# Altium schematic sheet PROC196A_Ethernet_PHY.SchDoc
size 431 x 279 mm; Date: Not shown in title block; ApprovedBy: Not shown in title block; CheckedBy: Not shown in title block; Author: Not shown in title block; CompanyName: Not shown in title block; Engineer: Not shown in title block; Organization: Not shown in title block; Address1: Not shown in title block; Address2: Not shown in title block; Address3: Not shown in title block; Address4: Not shown in title block; DocumentNumber: 12; Revision: Use project parameter SCH_Rev; SheetNumber: 12; SheetTotal: 25; PageSetup: Record=PageOptions¦CenterHorizontal=True¦CenterVertical=True¦PrintScale=1.00¦XCorrection=1.00¦YCorrection=1.00¦PrintKind=0¦BorderSize=5000000¦LeftOffset=0¦BottomOffset=0¦Orientation=2¦PaperLength=1000¦PaperWidth=1000¦Scale=100¦PaperSource=15¦PrintQuality=600¦MediaType=1¦DitherType=10¦PaperKind=Letter¦PrintScaleMode=1
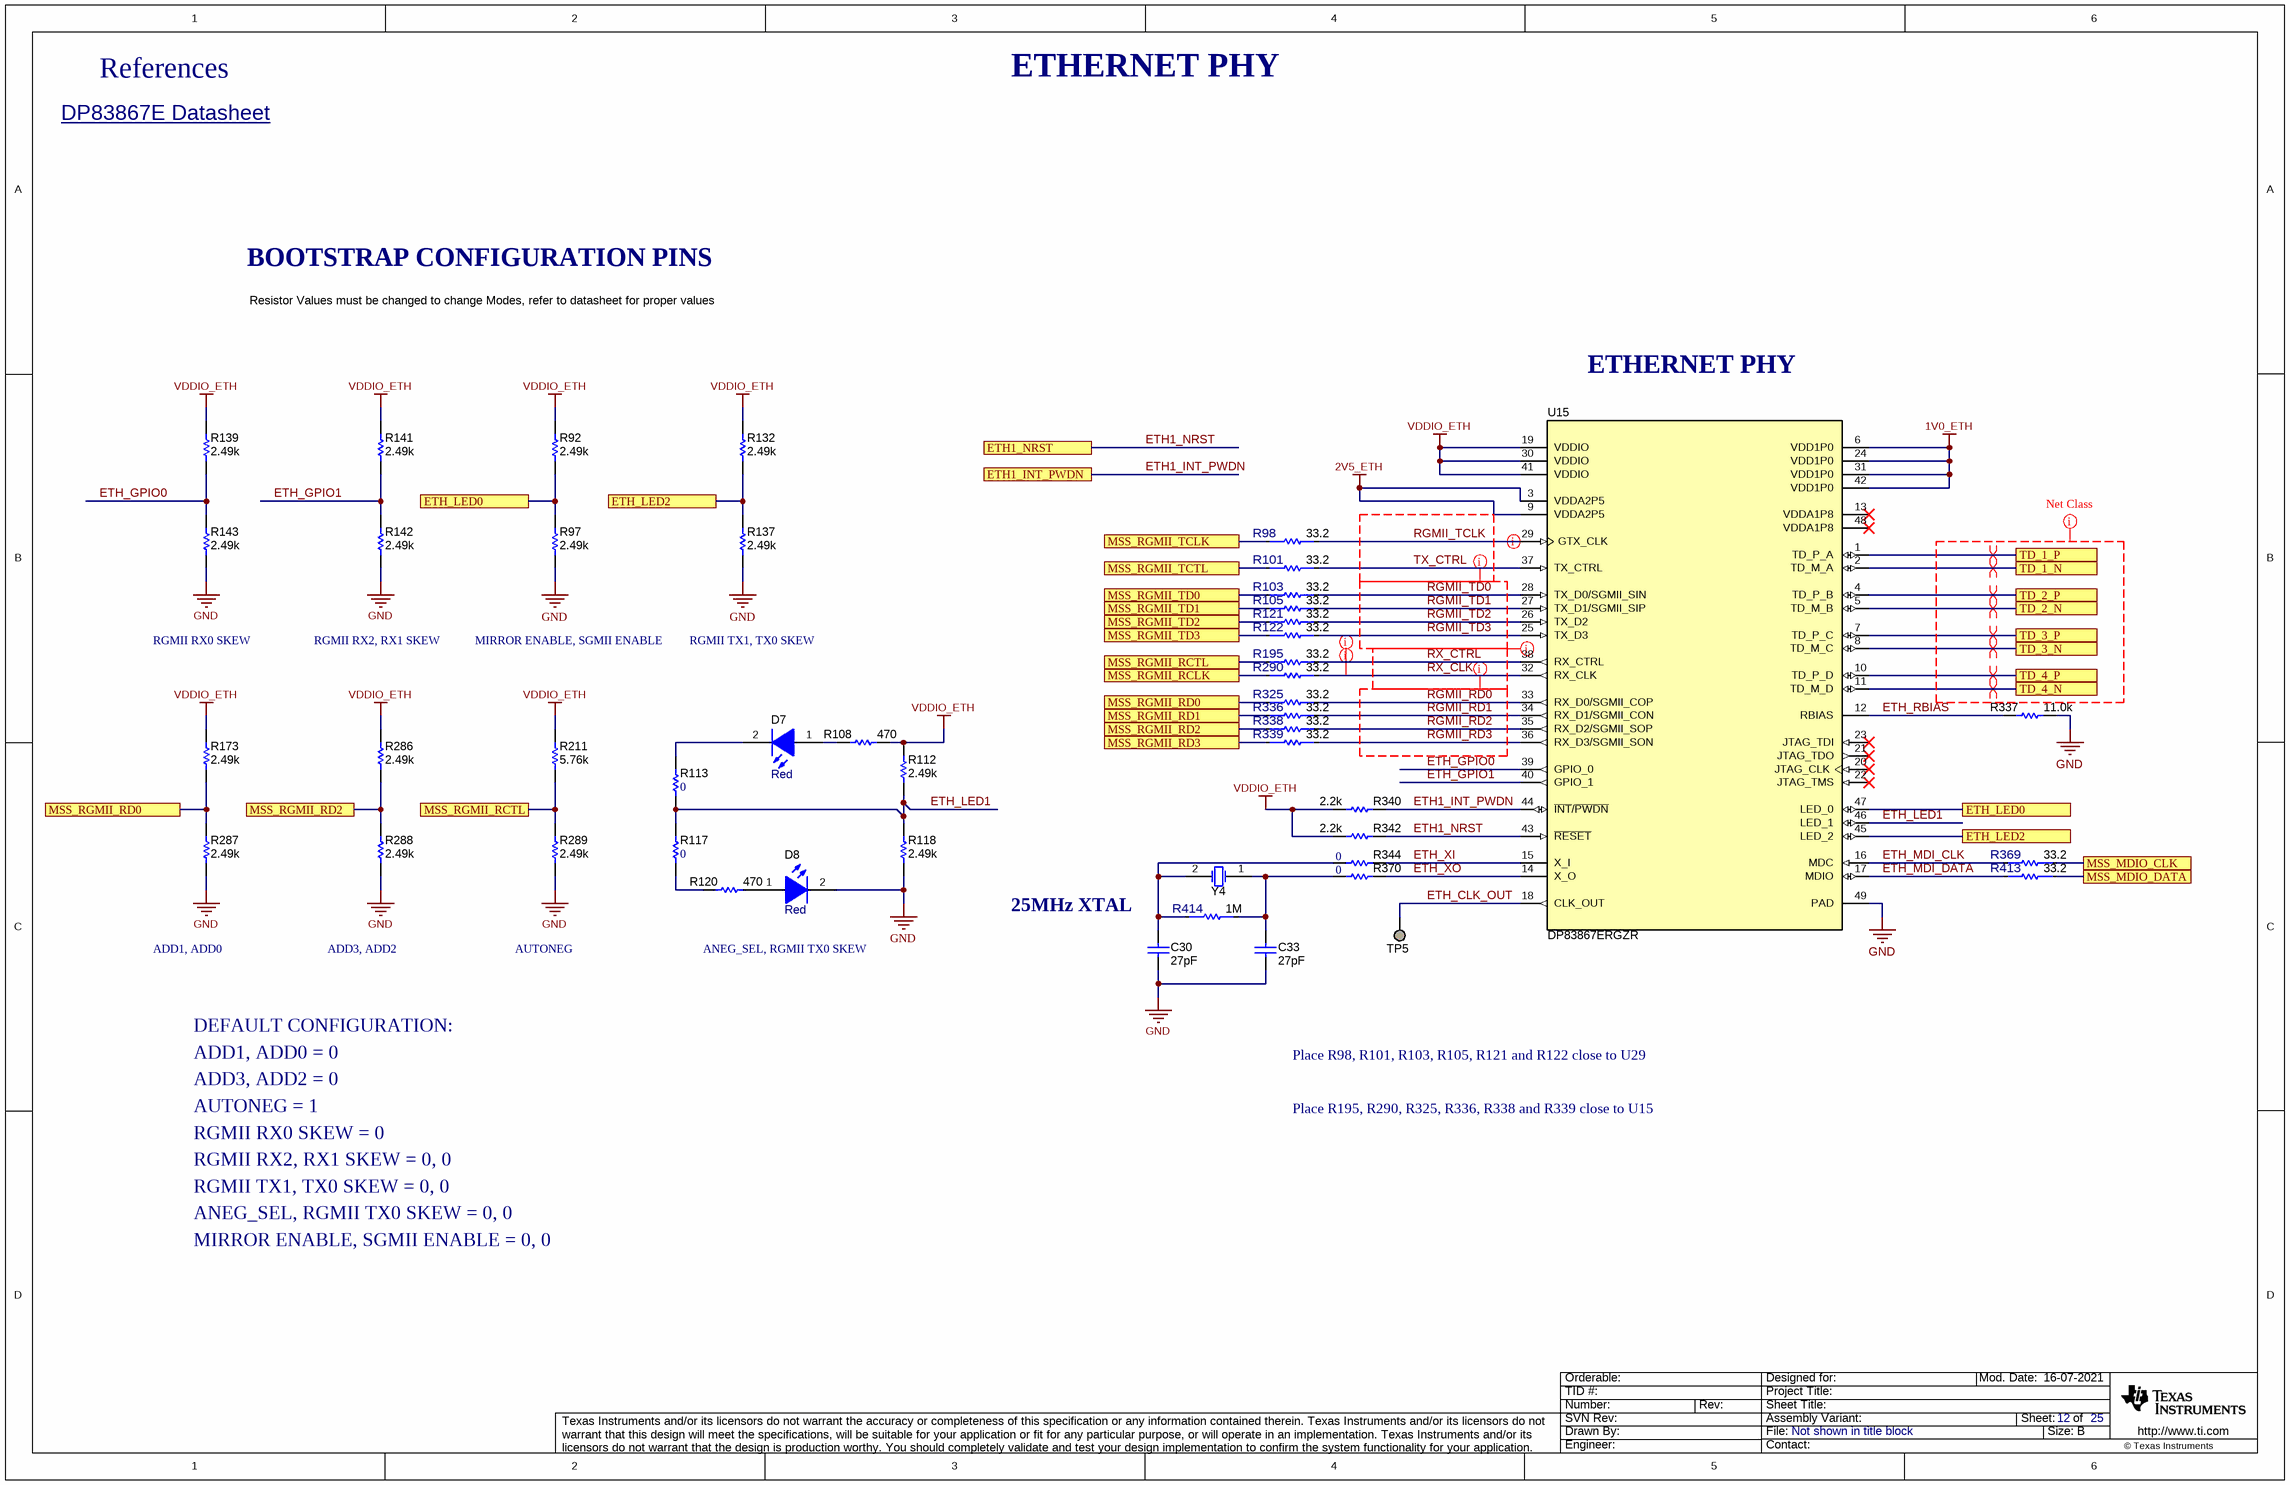
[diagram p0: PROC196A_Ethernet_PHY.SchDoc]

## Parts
C30  ValueDisplayed: 27pF  [0402L]  (hidden comment: GCM1555C1H270JA16D)
C33  ValueDisplayed: 27pF  [0402L]  (hidden comment: GCM1555C1H270JA16D)
D7  value Red  [LS L29K_Red]  (hidden comment: LS L29K-G1J2-1-Z)
D8  value Red  [LS L29K_Red]  (hidden comment: LS L29K-G1J2-1-Z)
R92  ValueDisplayed: 2.49k  [0402L]  (hidden comment: CRCW04022K49FKED)
R97  ValueDisplayed: 2.49k  [0402L]  (hidden comment: CRCW04022K49FKED)
R98  Res_ohm: 33.2  [FP-ERJ-1GNF33R2C_0201-MFG]  (hidden comment: ERJ-1GNF33R2C)
R101  Res_ohm: 33.2  [FP-ERJ-1GNF33R2C_0201-MFG]  (hidden comment: ERJ-1GNF33R2C)
R103  Res_ohm: 33.2  [FP-ERJ-1GNF33R2C_0201-MFG]  (hidden comment: ERJ-1GNF33R2C)
R105  Res_ohm: 33.2  [FP-ERJ-1GNF33R2C_0201-MFG]  (hidden comment: ERJ-1GNF33R2C)
R108  ValueDisplayed: 470  [0402L]  (hidden comment: ERJ-2RKF4700X)
R112  ValueDisplayed: 2.49k  [0402L]  (hidden comment: CRCW04022K49FKED)
R113  ValueDisplayed: 0  [0402L]  (hidden comment: ERJ-2GE0R00X)
R117  ValueDisplayed: 0  [0402L]  (hidden comment: ERJ-2GE0R00X)
R118  ValueDisplayed: 2.49k  [0402L]  (hidden comment: CRCW04022K49FKED)
R120  ValueDisplayed: 470  [0402L]  (hidden comment: ERJ-2RKF4700X)
R121  Res_ohm: 33.2  [FP-ERJ-1GNF33R2C_0201-MFG]  (hidden comment: ERJ-1GNF33R2C)
R122  Res_ohm: 33.2  [FP-ERJ-1GNF33R2C_0201-MFG]  (hidden comment: ERJ-1GNF33R2C)
R132  ValueDisplayed: 2.49k  [0402L]  (hidden comment: CRCW04022K49FKED)
R137  ValueDisplayed: 2.49k  [0402L]  (hidden comment: CRCW04022K49FKED)
R139  ValueDisplayed: 2.49k  [0402L]  (hidden comment: CRCW04022K49FKED)
R141  ValueDisplayed: 2.49k  [0402L]  (hidden comment: CRCW04022K49FKED)
R142  ValueDisplayed: 2.49k  [0402L]  (hidden comment: CRCW04022K49FKED)
R143  ValueDisplayed: 2.49k  [0402L]  (hidden comment: CRCW04022K49FKED)
R173  ValueDisplayed: 2.49k  [0402L]  (hidden comment: CRCW04022K49FKED)
R195  Res_ohm: 33.2  [FP-ERJ-1GNF33R2C_0201-MFG]  (hidden comment: ERJ-1GNF33R2C)
R211  ValueDisplayed: 5.76k  [0402L]  (hidden comment: CRCW04025K76FKED)
R286  ValueDisplayed: 2.49k  [0402L]  (hidden comment: CRCW04022K49FKED)
R287  ValueDisplayed: 2.49k  [0402L]  (hidden comment: CRCW04022K49FKED)
R288  ValueDisplayed: 2.49k  [0402L]  (hidden comment: CRCW04022K49FKED)
R289  ValueDisplayed: 2.49k  [0402L]  (hidden comment: CRCW04022K49FKED)
R290  Res_ohm: 33.2  [FP-ERJ-1GNF33R2C_0201-MFG]  (hidden comment: ERJ-1GNF33R2C)
R325  Res_ohm: 33.2  [FP-ERJ-1GNF33R2C_0201-MFG]  (hidden comment: ERJ-1GNF33R2C)
R336  Res_ohm: 33.2  [FP-ERJ-1GNF33R2C_0201-MFG]  (hidden comment: ERJ-1GNF33R2C)
R337  ValueDisplayed: 11.0k  [0402L]  (hidden comment: CRCW040211K0FKED)
R338  Res_ohm: 33.2  [FP-ERJ-1GNF33R2C_0201-MFG]  (hidden comment: ERJ-1GNF33R2C)
R339  Res_ohm: 33.2  [FP-ERJ-1GNF33R2C_0201-MFG]  (hidden comment: ERJ-1GNF33R2C)
R340  ValueDisplayed: 2.2k  [0402L]  (hidden comment: CRCW04022K20JNED)
R342  ValueDisplayed: 2.2k  [0402L]  (hidden comment: CRCW04022K20JNED)
R344  ValueDisplayed: 0  [0201L]  (hidden comment: CRCW02010000Z0ED)
R369  Res_ohm: 33.2  [FP-ERJ-1GNF33R2C_0201-MFG]  (hidden comment: ERJ-1GNF33R2C)
R370  ValueDisplayed: 0  [0201L]  (hidden comment: CRCW02010000Z0ED)
R413  Res_ohm: 33.2  [FP-ERJ-1GNF33R2C_0201-MFG]  (hidden comment: ERJ-1GNF33R2C)
R414  Res_ohm: 1M  [FP-CRCW06031M00FKEAC_0603-MFG]  (hidden comment: CRCW06031M00FKEAC)
TP5  TESTPOINT  [TP_25MIL-SMT]  (value not drawn)  (no BOM)
U15  DP83867ERGZR  [RGZ0048B]
Y4  ABM3-25.000MHZ-D2Y-T  [XTAL_ABM3]  (value not drawn)

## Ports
ETH1_INT_PWDN, ETH1_NRST, ETH_LED0, ETH_LED2, MSS_MDIO_CLK, MSS_MDIO_DATA, MSS_RGMII_RCLK, MSS_RGMII_RCTL, MSS_RGMII_RD0, MSS_RGMII_RD1, MSS_RGMII_RD2, MSS_RGMII_RD3, MSS_RGMII_TCLK, MSS_RGMII_TCTL, MSS_RGMII_TD0, MSS_RGMII_TD1, MSS_RGMII_TD2, MSS_RGMII_TD3, TD_1_N, TD_1_P, TD_2_N, TD_2_P, TD_3_N, TD_3_P, TD_4_N, TD_4_P

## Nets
1V0_ETH: U15.6(VDD1P0) U15.24(VDD1P0) U15.31(VDD1P0) U15.42(VDD1P0)
2V5_ETH: U15.3(VDDA2P5) U15.9(VDDA2P5)
GND: C30.2 C33.2 D8.2(K) R97.1 R118.1 R137.1 R142.1 R143.1 R287.1 R288.1 R289.1 R337.2 U15.49(PAD)
VDDIO_ETH: R92.2 R108.2 R112.2 R132.2 R139.2 R141.2 R173.2 R211.2 R286.2 R340.2 R342.2 U15.19(VDDIO) U15.30(VDDIO) U15.41(VDDIO)
ETH1_INT_PWDN: R340.1 U15.44(~{INT}/~{PWDN}) ; port ETH1_INT_PWDN
ETH1_NRST: R342.1 U15.43(~{RESET}) ; port ETH1_NRST
ETH_CLK_OUT: TP5.1 U15.18(CLK_OUT)
ETH_GPIO0: R139.1 R143.2 U15.39(GPIO_0)
ETH_GPIO1: R141.1 R142.2 U15.40(GPIO_1)
ETH_LED0: R92.1 R97.2 U15.47(LED_0) ; port ETH_LED0
ETH_LED1: R112.1 R113.1 R117.2 R118.2 U15.46(LED_1)
ETH_LED2: R132.1 R137.2 U15.45(LED_2) ; port ETH_LED2
ETH_MDI_CLK: R369.2 U15.16(MDC)
ETH_MDI_DATA: R413.2 U15.17(MDIO)
ETH_RBIAS: R337.1 U15.12(RBIAS)
ETH_XI: R344.2 U15.15(X_I)
ETH_XO: R370.2 U15.14(X_O)
MSS_MDIO_CLK: R369.1 ; port MSS_MDIO_CLK
MSS_MDIO_DATA: R413.1 ; port MSS_MDIO_DATA
MSS_RGMII_RCLK: R290.1 ; port MSS_RGMII_RCLK
MSS_RGMII_RCTL: R195.1 R211.1 R289.2 ; port MSS_RGMII_RCTL
MSS_RGMII_RD0: R173.1 R287.2 R325.1 ; port MSS_RGMII_RD0
MSS_RGMII_RD1: R336.1 ; port MSS_RGMII_RD1
MSS_RGMII_RD2: R286.1 R288.2 R338.1 ; port MSS_RGMII_RD2
MSS_RGMII_RD3: R339.1 ; port MSS_RGMII_RD3
MSS_RGMII_TCLK: R98.1 ; port MSS_RGMII_TCLK
MSS_RGMII_TCTL: R101.1 ; port MSS_RGMII_TCTL
MSS_RGMII_TD0: R103.1 ; port MSS_RGMII_TD0
MSS_RGMII_TD1: R105.1 ; port MSS_RGMII_TD1
MSS_RGMII_TD2: R121.1 ; port MSS_RGMII_TD2
MSS_RGMII_TD3: R122.1 ; port MSS_RGMII_TD3
RGMII_RD0: R325.2 U15.33(RX_D0/SGMII_COP)
RGMII_RD1: R336.2 U15.34(RX_D1/SGMII_CON)
RGMII_RD2: R338.2 U15.35(RX_D2/SGMII_SOP)
RGMII_RD3: R339.2 U15.36(RX_D3/SGMII_SON)
RGMII_TCLK: R98.2 U15.29(GTX_CLK)
RGMII_TD0: R103.2 U15.28(TX_D0/SGMII_SIN)
RGMII_TD1: R105.2 U15.27(TX_D1/SGMII_SIP)
RGMII_TD2: R121.2 U15.26(TX_D2)
RGMII_TD3: R122.2 U15.25(TX_D3)
RX_CLK: R290.2 U15.32(RX_CLK)
RX_CTRL: R195.2 U15.38(RX_CTRL)
TD_1_N: U15.2(TD_M_A) ; port TD_1_N
TD_1_P: U15.1(TD_P_A) ; port TD_1_P
TD_2_N: U15.5(TD_M_B) ; port TD_2_N
TD_2_P: U15.4(TD_P_B) ; port TD_2_P
TD_3_N: U15.8(TD_M_C) ; port TD_3_N
TD_3_P: U15.7(TD_P_C) ; port TD_3_P
TD_4_N: U15.11(TD_M_D) ; port TD_4_N
TD_4_P: U15.10(TD_P_D) ; port TD_4_P
TX_CTRL: R101.2 U15.37(TX_CTRL)
NetC30_1: C30.1 R344.1 R414.1 Y4.2(OSC2)
NetC33_1: C33.1 R370.1 R414.2 Y4.1(OSC1)
NetD7_1: D7.1(A) R108.1
NetD7_2: D7.2(K) R113.2
NetD8_1: D8.1(A) R120.2
NetR117_1: R117.1 R120.1

Not connected (* = marked no-connect by the designer): U15 13(VDDA1P8)* 20(JTAG_CLK)* 21(JTAG_TDO)* 22(JTAG_TMS)* 23(JTAG_TDI)* 48(VDDA1P8)*

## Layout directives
net class RGMII; net class RGMII_TX_RX: RGMII_RD0, RGMII_RD1, RGMII_RD2, RGMII_RD3, RGMII_TD0, RGMII_TD1, RGMII_TD2, RGMII_TD3
net class RGMII: (no net found under the mark), RX_CLK, RX_CTRL
differential pair: TD_1_N, TD_1_P, TD_2_N, TD_2_P, TD_3_N, TD_3_P, TD_4_N, TD_4_P
net class RGMII_TX_RX: RGMII_TCLK, RGMII_TD0, RGMII_TD1, RGMII_TD2, RGMII_TD3

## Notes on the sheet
- References
- ETHERNET PHY
- DP83867E Datasheet <http://www.ti.com/lit/ds/symlink/dp83867e.pdf>
- BOOTSTRAP CONFIGURATION PINS
- Resistor Values must be changed to change Modes, refer to datasheet for proper values
- RGMII RX0 SKEW
- RGMII RX2, RX1 SKEW
- MIRROR ENABLE, SGMII ENABLE
- RGMII TX1, TX0 SKEW
- ADD1, ADD0
- ADD3, ADD2
- AUTONEG
- ANEG_SEL, RGMII TX0 SKEW
- 25MHz XTAL
- DEFAULT CONFIGURATION:
- ADD1, ADD0 = 0
- ADD3, ADD2 = 0
- Place R98, R101, R103, R105, R121 and R122 close to U29
- AUTONEG = 1
- RGMII RX2, RX1 SKEW = 0, 0
- RGMII RX0 SKEW = 0
- Place R195, R290, R325, R336, R338 and R339 close to U15
- RGMII TX1, TX0 SKEW = 0, 0
- ANEG_SEL, RGMII TX0 SKEW = 0, 0
- MIRROR ENABLE, SGMII ENABLE = 0, 0

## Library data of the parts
C30 C33 = CMP-0860920-1: CAP, CERM, 27 pF, 50 V,+/- 5%, C0G/NP0, AEC-Q200 Grade 1, 0402; Manufacturer: MuRata; AEC Grade: 1; SizeZ_mm: 0.6; U/M: EA; Value: 27pF; SizeY_mm: 0.5; TaMax_C: 125°C; Polarized: N; AEC Qualified: Y; Cap_Case: 0402; AEC Category: Q200; Value2: 50V; SizeAreaWB_mm2: 3; TaMin_C: -55°C
D7 D8 = CMP-0002902-2: LED, Red, SMD; Manufacturer: OSRAM; Tjmax_C: 110°C; Vf_V: 1.8V; Vr_V: 12V; Io_A: 20mA; Angle: 160; Value1: W
R92 R97 R112 R118 R132 R137 R139 R141-R143 R173 R286-R289 = CMP-0026237-2: RES, 2.49 k, 1%, 0.063 W, AEC-Q200 Grade 0, 0402; Manufacturer: Vishay-Dale; Power_W: 63mW; TempCo: 100 ppm/C; Value_Code: 2k49; Value: 2.49k; EIA_Code: E96; SizeX_mm: 1; SizeY_mm: 0.5; SizeZ_mm: 0.6; Value2: 0.063W; AEC Qualified: Y; VDC_V: 50V; AEC Category: Q200; AEC Grade: 0
R98 R101 R103 R105 R121 R122 R195 R290 R325 R336 R338 R339 R369 R413 = CMP-0089575-2: Res Thick Film 0201 33.2 Ohm 1% 0.05W(1/20W) ±200ppm/C Pad SMD Automotive T/R; Manufacturer: Panasonic; TempCo: 200ppm/°C; VDC_V: 25V; AEC Qualified: Yes; SizeZ_mm: 0.26mm; Power_W: 50mW; AEC Grade: Grade 1; Value: 33.2
R108 R120 = CMP-0026699-1: RES, 470, 1%, 0.1 W, AEC-Q200 Grade 0, 0402; Manufacturer: Panasonic; Power_W: 100mW; TempCo: 100 ppm/C; Value_Code: 470R; U/M: EA; Value: 470; SizeX_mm: 1; SizeY_mm: 0.5; SizeZ_mm: 0.6; Value2: 0.1W; AEC Qualified: Y; VDC_V: 50V; AEC Grade: 0; AEC Category: Q200
R113 R117 = CMP-0026992-3: RES, 0, 5%, 0.1 W, AEC-Q200 Grade 0, 0402; Manufacturer: Panasonic; Power_W: 100mW; TempCo: 600 ppm/C; Value_Code: 0000; Value: 0; EIA_Code: E24; SizeX_mm: 1; SizeY_mm: 0.5; SizeZ_mm: 0.6; Value2: 0.1W; CompType: Resistor; AEC Qualified: Y; VDC_V: 50V; AEC Category: Q200; SizeAreaWB_mm2: 3; INSTALLATION: DNP
R211 = CMP-0026468-2: RES, 5.76 k, 1%, 0.063 W, AEC-Q200 Grade 0, 0402; Manufacturer: Vishay-Dale; Power_W: 63mW; TempCo: 100 ppm/C; Value_Code: 5k76; Value: 5.76k; EIA_Code: E96; SizeX_mm: 1; SizeY_mm: 0.5; SizeZ_mm: 0.6; Value2: 0.063W; AEC Qualified: Y; VDC_V: 50V; AEC Category: Q200; AEC Grade: 0
R337 = CMP-0025975-3: RES, 11.0 k, 1%, 0.063 W, AEC-Q200 Grade 0, 0402; Manufacturer: Vishay-Dale; Power_W: 63mW; TempCo: 100 ppm/C; Value_Code: 11k0; Value: 11.0k; EIA_Code: E96; Res_ohm: 11k; SizeX_mm: 1; SizeY_mm: 0.5; SizeZ_mm: 0.6; Value2: 0.063W; AEC Qualified: Y; VDC_V: 50V; AEC Category: Q200; AEC Grade: 0
R340 R342 = CMP-0026890-5: RES, 2.2 k, 5%, 0.063 W, AEC-Q200 Grade 0, 0402; Manufacturer: Vishay-Dale; Power_W: 63mW; TempCo: 200 ppm/C; Value_Code: 2k20; Value: 2.2k; EIA_Code: E24; SizeX_mm: 1; SizeY_mm: 0.5; SizeZ_mm: 0.6; Value2: 0.063W; AEC Qualified: Y; VDC_V: 50V; AEC Category: Q200; AEC Grade: 0
R344 R370 = CMP-0027008-4: RES, 0, 5%, 0.05 W, 0201; Manufacturer: Vishay-Dale; Power_W: 50mW; TempCo: ppm/C; Value_Code: 0000; Value: 0; EIA_Code: E24; SizeX_mm: 0.6; SizeY_mm: 0.3; SizeZ_mm: 0.26; Value2: 0.05W; SizeArea_mm2: 0.18; AEC Qualified: N; AEC Category: Q200
R414 = CMP-0089574-2: Res Thick Film 0603 1M Ohm 1% 1/10W ±100ppm/°C Molded SMD Paper T/R; Manufacturer: Vishay; AEC Qualified: No; Power_W: 100mW; AEC Grade: NA; SizeZ_mm: 0.55mm; VDC_V: 75V
TP5 = CMP-0078143-3: TEST POINT.  No entry in BOM.
U15 = CMP-0076013-2: Extended Temperature Gigabit Ethernet PHY with SGMII, RGZ0048B (VQFN-48); Manufacturer: Texas Instruments; Alternate PartNumber: DP83867ERGZT; SizeX_mm: 7; CompType: IC; SizeZ_mm: 1; SizeArea_mm2: 49; SizeAreaWB_mm2: 81; U/M: EA
Y4 = CMP-0004620-3: Crystal, 25 MHz, 18 pF, SMD; Manufacturer: Abracon Corporation; TaMin_C: -40°C; Frequency Stability: +/-30ppm; Frequency_Fixed: 25MHz; TaMax_C: 85°C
